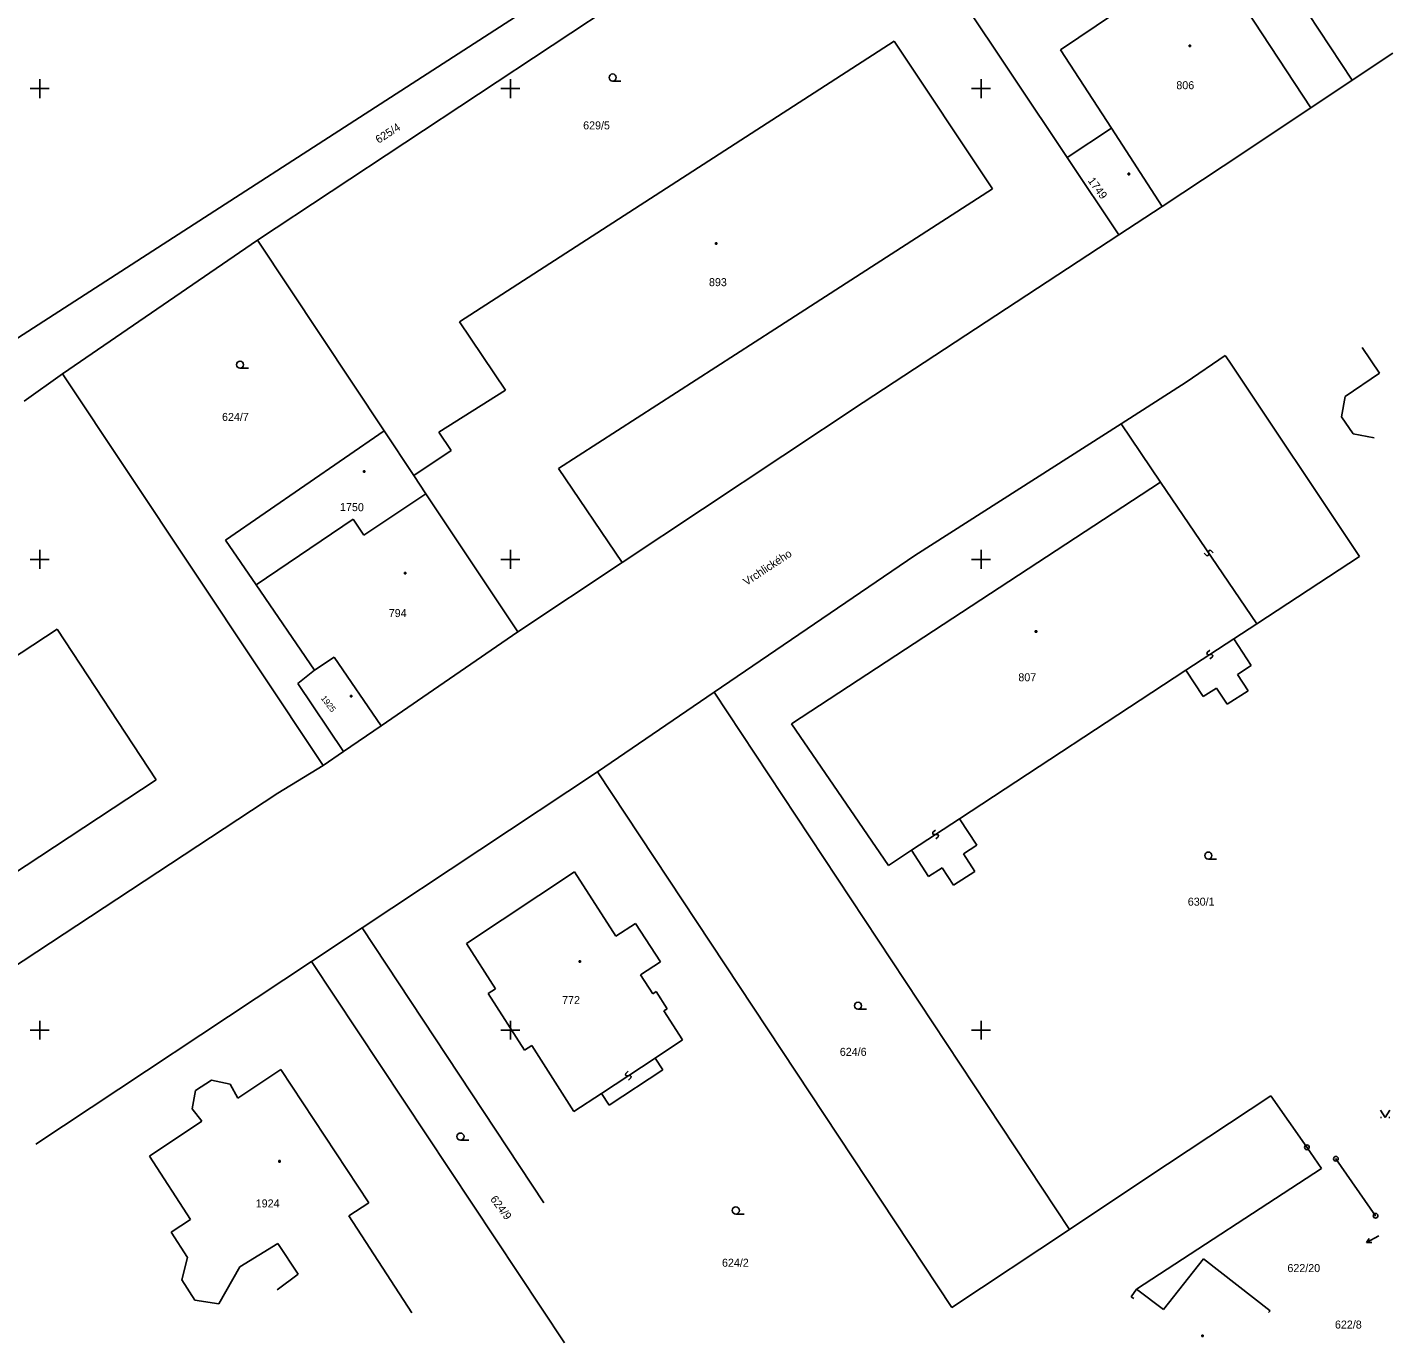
# Model space of a CAD drawing. Extents: x -493352 to -492964, y -1127001 to -1126712.
# Drawn here: x -493050.8 to -492963.8, y -1126999.9 to -1126916.1 of the extents above; entities that cross this region are included whole.
import ezdxf

# ---------------------------------------------------------------- set-up
doc = ezdxf.new("R2010")
doc.units = 0
doc.layers.add('katastrální mapa', color=7, linetype='Continuous')
doc.layers.add('síť', color=7, linetype='Continuous')

msp = doc.modelspace()

# ---------------------------------------------------------------- linework, layer by layer
at = {"layer": 'katastrální mapa'}
for p, q in [((-492982.85, -1126894.43), (-492966.34, -1126919.47)), ((-493036.12, -1126929.67), (-492997.86, -1126904.36)), ((-492997.86, -1126904.36), (-492984.51, -1126924.39)), ((-493063.66, -1126943.8), (-493007.98, -1126907.88)), ((-492974.44, -1126912.93), (-492968.97, -1126921.22)), ((-492984.93, -1126917.52), (-492981.49, -1126915.21)), ((-493009.39, -1126925.92), (-492995.53, -1126916.98)), ((-492995.53, -1126916.98), (-492989.27, -1126926.39)), ((-492984.93, -1126917.52), (-492981.68, -1126922.53)), ((-492976.74, -1126917.23), (-492976.65, -1126917.23)), ((-492976.74, -1126917.32), (-492976.74, -1126917.23)), ((-492976.65, -1126917.32), (-492976.74, -1126917.32)), ((-492976.65, -1126917.23), (-492976.65, -1126917.32)), ((-492966.34, -1126919.47), (-492963.76, -1126917.75)), ((-493013.48, -1126919.52), (-493012.95, -1126919.52)), ((-492968.97, -1126921.22), (-492966.34, -1126919.47)), ((-492974.56, -1126924.95), (-492968.97, -1126921.22)), ((-492984.51, -1126924.39), (-492981.68, -1126922.53)), ((-492981.68, -1126922.53), (-492978.46, -1126927.51)), ((-492984.51, -1126924.39), (-492981.22, -1126929.32)), ((-492978.46, -1126927.51), (-492974.56, -1126924.95)), ((-493023.25, -1126934.87), (-493009.39, -1126925.92)), ((-492980.62, -1126925.4), (-492980.53, -1126925.4)), ((-492980.62, -1126925.49), (-492980.62, -1126925.4)), ((-492980.53, -1126925.49), (-492980.62, -1126925.49)), ((-492980.53, -1126925.4), (-492980.53, -1126925.49)), ((-493003.14, -1126935.33), (-492989.27, -1126926.39)), ((-492981.22, -1126929.32), (-492978.46, -1126927.51)), ((-493048.54, -1126938.17), (-493036.12, -1126929.67)), ((-493036.12, -1126929.67), (-493028.04, -1126941.82)), ((-492997.52, -1126940.01), (-492981.22, -1126929.32)), ((-493006.92, -1126929.82), (-493006.83, -1126929.82)), ((-493006.92, -1126929.91), (-493006.92, -1126929.82)), ((-493006.83, -1126929.91), (-493006.92, -1126929.91)), ((-493006.83, -1126929.82), (-493006.83, -1126929.91)), ((-493023.25, -1126934.87), (-493020.31, -1126939.22)), ((-493016.93, -1126944.22), (-493003.14, -1126935.33)), ((-492965.71, -1126936.49), (-492964.6, -1126938.13)), ((-492976.92, -1126938.7), (-492974.44, -1126937.01)), ((-492974.44, -1126937.01), (-492974.18, -1126937.38)), ((-492974.18, -1126937.38), (-492965.88, -1126949.81)), ((-493050.98, -1126939.91), (-493048.54, -1126938.17)), ((-493048.54, -1126938.17), (-493031.94, -1126963.13)), ((-493037.23, -1126937.82), (-493036.7, -1126937.82)), ((-492966.79, -1126939.62), (-492964.6, -1126938.13)), ((-493024.56, -1126941.9), (-493020.31, -1126939.22)), ((-492981.07, -1126941.36), (-492976.92, -1126938.7)), ((-493012.88, -1126950.21), (-492997.52, -1126940.01)), ((-492967.03, -1126940.91), (-492966.79, -1126939.62)), ((-492967.03, -1126940.91), (-492966.27, -1126942.01)), ((-493038.16, -1126948.78), (-493028.04, -1126941.82)), ((-493028.04, -1126941.82), (-493026.16, -1126944.65)), ((-492994.21, -1126949.76), (-492981.07, -1126941.36)), ((-492981.07, -1126941.36), (-492978.55, -1126945.08)), ((-493024.56, -1126941.9), (-493023.78, -1126943.07)), ((-492966.27, -1126942.01), (-492964.94, -1126942.25)), ((-493026.16, -1126944.65), (-493023.78, -1126943.07)), ((-493029.37, -1126944.36), (-493029.28, -1126944.36)), ((-493029.37, -1126944.45), (-493029.37, -1126944.36)), ((-493029.28, -1126944.45), (-493029.37, -1126944.45)), ((-493029.28, -1126944.36), (-493029.28, -1126944.45)), ((-493016.93, -1126944.22), (-493012.88, -1126950.21)), ((-493026.16, -1126944.65), (-493025.38, -1126945.82)), ((-493002.07, -1126960.49), (-492978.55, -1126945.08)), ((-492978.55, -1126945.08), (-492972.43, -1126954.11)), ((-493029.33, -1126948.45), (-493025.38, -1126945.82)), ((-493025.38, -1126945.82), (-493019.52, -1126954.62)), ((-493036.21, -1126951.63), (-493030.01, -1126947.43)), ((-493030.01, -1126947.43), (-493029.33, -1126948.45)), ((-493038.16, -1126948.78), (-493036.21, -1126951.63)), ((-492975.63, -1126949.76), (-492975.77, -1126949.61)), ((-492975.48, -1126949.45), (-492975.5, -1126949.53)), ((-492975.5, -1126949.53), (-492975.48, -1126949.66)), ((-492975.48, -1126949.66), (-492975.5, -1126949.74)), ((-492975.43, -1126949.41), (-492975.48, -1126949.45)), ((-492975.35, -1126949.43), (-492975.43, -1126949.41)), ((-492975.21, -1126949.58), (-492975.35, -1126949.43)), ((-493019.52, -1126954.62), (-493012.88, -1126950.21)), ((-493007, -1126958.47), (-492994.21, -1126949.76)), ((-492975.55, -1126949.78), (-492975.63, -1126949.76)), ((-492975.5, -1126949.74), (-492975.55, -1126949.78)), ((-492972.43, -1126954.11), (-492965.88, -1126949.81)), ((-493026.75, -1126950.84), (-493026.66, -1126950.84)), ((-493026.75, -1126950.93), (-493026.75, -1126950.84)), ((-493026.66, -1126950.93), (-493026.75, -1126950.93)), ((-493026.66, -1126950.84), (-493026.66, -1126950.93)), ((-493036.21, -1126951.63), (-493032.48, -1126957.07)), ((-493063.3, -1126963.95), (-493048.88, -1126954.44)), ((-493048.88, -1126954.44), (-493042.57, -1126964.05)), ((-493028.24, -1126960.6), (-493019.52, -1126954.62)), ((-492986.54, -1126954.55), (-492986.45, -1126954.55)), ((-492986.54, -1126954.64), (-492986.54, -1126954.55)), ((-492986.45, -1126954.64), (-492986.54, -1126954.64)), ((-492986.45, -1126954.55), (-492986.45, -1126954.64)), ((-492973.89, -1126955.07), (-492972.43, -1126954.11)), ((-492976.94, -1126957.07), (-492973.89, -1126955.07)), ((-492975.42, -1126955.79), (-492975.58, -1126955.93)), ((-492973.89, -1126955.07), (-492972.79, -1126956.77)), ((-493032.48, -1126957.07), (-493031.24, -1126956.23)), ((-493031.24, -1126956.23), (-493028.24, -1126960.6)), ((-492975.58, -1126955.93), (-492975.6, -1126956.01)), ((-492975.6, -1126956.01), (-492975.56, -1126956.06)), ((-492975.56, -1126956.06), (-492975.48, -1126956.08)), ((-492975.48, -1126956.08), (-492975.35, -1126956.06)), ((-492975.25, -1126956.21), (-492975.41, -1126956.35)), ((-492975.35, -1126956.06), (-492975.27, -1126956.08)), ((-492975.27, -1126956.08), (-492975.23, -1126956.13)), ((-492975.23, -1126956.13), (-492975.25, -1126956.21)), ((-493033.54, -1126957.91), (-493032.48, -1126957.07)), ((-492991.37, -1126966.53), (-492976.94, -1126957.07)), ((-492976.94, -1126957.07), (-492975.84, -1126958.75)), ((-492973.65, -1126957.33), (-492972.79, -1126956.77)), ((-492973.65, -1126957.33), (-492972.97, -1126958.37)), ((-493033.54, -1126957.91), (-493030.63, -1126962.24)), ((-492975.84, -1126958.75), (-492974.98, -1126958.2)), ((-492974.98, -1126958.2), (-492974.31, -1126959.22)), ((-492974.31, -1126959.22), (-492972.97, -1126958.37)), ((-493030.19, -1126958.67), (-493030.1, -1126958.67)), ((-493030.19, -1126958.76), (-493030.19, -1126958.67)), ((-493030.1, -1126958.76), (-493030.19, -1126958.76)), ((-493030.1, -1126958.67), (-493030.1, -1126958.76)), ((-493014.44, -1126963.54), (-493007, -1126958.47)), ((-493007, -1126958.47), (-492984.37, -1126992.7)), ((-493030.63, -1126962.24), (-493028.24, -1126960.6)), ((-493002.07, -1126960.49), (-492995.9, -1126969.5)), ((-493031.94, -1126963.13), (-493030.63, -1126962.24)), ((-493034.83, -1126964.91), (-493031.94, -1126963.13)), ((-493029.45, -1126973.48), (-493014.44, -1126963.54)), ((-493014.44, -1126963.54), (-492991.86, -1126997.68)), ((-493057.08, -1126973.59), (-493042.57, -1126964.05)), ((-493055.85, -1126978.73), (-493034.83, -1126964.91)), ((-492994.43, -1126968.54), (-492991.37, -1126966.53)), ((-492991.37, -1126966.53), (-492990.27, -1126968.22)), ((-492993.07, -1126967.39), (-492993.08, -1126967.48)), ((-492993.08, -1126967.48), (-492993.05, -1126967.53)), ((-492992.91, -1126967.25), (-492993.07, -1126967.39)), ((-492993.05, -1126967.53), (-492992.97, -1126967.54)), ((-492992.97, -1126967.54), (-492992.83, -1126967.53)), ((-492992.73, -1126967.68), (-492992.89, -1126967.82)), ((-492992.83, -1126967.53), (-492992.75, -1126967.54)), ((-492992.75, -1126967.54), (-492992.72, -1126967.59)), ((-492992.72, -1126967.59), (-492992.73, -1126967.68)), ((-492995.9, -1126969.5), (-492994.43, -1126968.54)), ((-492994.43, -1126968.54), (-492993.34, -1126970.22)), ((-492991.12, -1126968.77), (-492990.27, -1126968.22)), ((-492991.12, -1126968.77), (-492990.39, -1126969.9)), ((-492993.34, -1126970.22), (-492992.48, -1126969.66)), ((-492992.48, -1126969.66), (-492991.75, -1126970.77)), ((-492975.51, -1126969.1), (-492974.98, -1126969.1)), ((-493022.8, -1126974.48), (-493015.92, -1126969.91)), ((-493015.92, -1126969.91), (-493013.28, -1126974.01)), ((-492991.75, -1126970.77), (-492990.39, -1126969.9)), ((-493013.28, -1126974.01), (-493012.02, -1126973.2)), ((-493012.02, -1126973.2), (-493010.44, -1126975.65)), ((-493032.67, -1126975.62), (-493029.45, -1126973.48)), ((-493029.45, -1126973.48), (-493017.86, -1126991)), ((-493022.8, -1126974.48), (-493020.95, -1126977.36)), ((-493050.24, -1126987.27), (-493032.67, -1126975.62)), ((-493032.67, -1126975.62), (-493016.55, -1126999.92)), ((-493015.61, -1126975.58), (-493015.52, -1126975.58)), ((-493015.61, -1126975.67), (-493015.61, -1126975.58)), ((-493015.52, -1126975.67), (-493015.61, -1126975.67)), ((-493015.52, -1126975.58), (-493015.52, -1126975.67)), ((-493011.7, -1126976.47), (-493010.44, -1126975.65)), ((-493011.7, -1126976.47), (-493010.91, -1126977.69)), ((-493021.42, -1126977.66), (-493020.95, -1126977.36)), ((-493010.91, -1126977.69), (-493010.7, -1126977.55)), ((-493010.7, -1126977.55), (-493010, -1126978.64)), ((-493021.42, -1126977.66), (-493019.1, -1126981.28)), ((-493010.21, -1126978.78), (-493010, -1126978.64)), ((-493010.21, -1126978.78), (-493009.02, -1126980.63)), ((-492997.84, -1126978.67), (-492997.31, -1126978.67)), ((-493019.1, -1126981.28), (-493018.64, -1126980.99)), ((-493018.64, -1126980.99), (-493015.96, -1126985.18)), ((-493010.77, -1126981.78), (-493009.02, -1126980.63)), ((-493014.2, -1126984.03), (-493010.77, -1126981.78)), ((-493010.77, -1126981.78), (-493010.28, -1126982.53)), ((-493037.37, -1126984.33), (-493034.64, -1126982.51)), ((-493034.64, -1126982.51), (-493029.03, -1126991.01)), ((-493013.71, -1126984.78), (-493010.28, -1126982.53)), ((-493012.65, -1126982.76), (-493012.67, -1126982.85)), ((-493012.49, -1126982.62), (-493012.65, -1126982.76)), ((-493040.06, -1126983.84), (-493039.04, -1126983.2)), ((-493039.04, -1126983.2), (-493037.87, -1126983.45)), ((-493037.87, -1126983.45), (-493037.37, -1126984.33)), ((-493012.67, -1126982.85), (-493012.63, -1126982.9)), ((-493012.63, -1126982.9), (-493012.55, -1126982.91)), ((-493012.55, -1126982.91), (-493012.42, -1126982.9)), ((-493012.32, -1126983.05), (-493012.48, -1126983.19)), ((-493012.42, -1126982.9), (-493012.34, -1126982.91)), ((-493012.34, -1126982.91), (-493012.3, -1126982.96)), ((-493012.3, -1126982.96), (-493012.32, -1126983.05)), ((-493040.28, -1126985.01), (-493040.06, -1126983.84)), ((-493015.96, -1126985.18), (-493014.2, -1126984.03)), ((-493014.2, -1126984.03), (-493013.71, -1126984.78)), ((-492979.44, -1126989.42), (-492971.52, -1126984.19)), ((-492971.52, -1126984.19), (-492969.23, -1126987.47)), ((-493040.28, -1126985.01), (-493039.67, -1126985.8)), ((-492964.54, -1126985.11), (-492964.24, -1126985.56)), ((-492964.24, -1126985.56), (-492963.94, -1126985.11)), ((-493043, -1126988.04), (-493039.67, -1126985.8)), ((-492964.54, -1126985.56), (-492964.48, -1126985.56)), ((-492964, -1126985.56), (-492963.94, -1126985.56)), ((-493023.18, -1126987.01), (-493022.65, -1126987.01)), ((-492969.23, -1126987.47), (-492968.29, -1126988.83)), ((-493043, -1126988.04), (-493040.39, -1126992.07)), ((-493034.76, -1126988.32), (-493034.67, -1126988.32)), ((-493034.76, -1126988.41), (-493034.76, -1126988.32)), ((-493034.67, -1126988.41), (-493034.76, -1126988.41)), ((-493034.67, -1126988.32), (-493034.67, -1126988.41)), ((-492980.09, -1126996.51), (-492968.29, -1126988.83)), ((-492964.85, -1126991.83), (-492967.38, -1126988.2)), ((-492984.37, -1126992.7), (-492979.44, -1126989.42)), ((-493030.29, -1126991.84), (-493029.03, -1126991.01)), ((-493041.62, -1126992.88), (-493040.39, -1126992.07)), ((-493030.29, -1126991.84), (-493026.28, -1126998.01)), ((-493005.63, -1126991.72), (-493005.1, -1126991.72)), ((-493041.62, -1126992.88), (-493040.57, -1126994.5)), ((-492991.86, -1126997.68), (-492984.37, -1126992.7)), ((-492964.65, -1126993.11), (-492965.44, -1126993.54)), ((-493037.24, -1126995.08), (-493034.82, -1126993.6)), ((-493034.82, -1126993.6), (-493033.52, -1126995.56)), ((-492965.44, -1126993.54), (-492965.25, -1126993.27)), ((-492965.44, -1126993.54), (-492965.1, -1126993.53)), ((-493040.93, -1126995.91), (-493040.57, -1126994.5)), ((-492978.36, -1126997.81), (-492975.82, -1126994.57)), ((-492975.82, -1126994.57), (-492971.58, -1126997.89)), ((-493038.58, -1126997.45), (-493037.24, -1126995.08)), ((-493034.87, -1126996.56), (-493033.52, -1126995.56)), ((-493040.93, -1126995.91), (-493040.11, -1126997.22)), ((-492980.44, -1126996.99), (-492980.09, -1126996.51)), ((-492980.09, -1126996.51), (-492978.36, -1126997.81)), ((-493040.11, -1126997.22), (-493038.58, -1126997.45)), ((-492980.44, -1126996.99), (-492980.27, -1126997.11)), ((-492971.58, -1126997.89), (-492971.67, -1126997.99)), ((-492975.93, -1126999.44), (-492975.84, -1126999.44)), ((-492975.93, -1126999.53), (-492975.93, -1126999.44)), ((-492975.84, -1126999.53), (-492975.93, -1126999.53)), ((-492975.84, -1126999.44), (-492975.84, -1126999.53))]:
    msp.add_line(p, q, dxfattribs=at)
for centre, radius in [((-493013.48, -1126919.295), 0.225), ((-493037.23, -1126937.595), 0.225), ((-492975.51, -1126968.875), 0.225), ((-492997.84, -1126978.445), 0.225), ((-493023.18, -1126986.785), 0.225), ((-492969.23, -1126987.47), 0.15), ((-492969.23, -1126987.47), 0.003), ((-492967.38, -1126988.2), 0.15), ((-492967.38, -1126988.2), 0.003), ((-493005.63, -1126991.495), 0.225), ((-492964.85, -1126991.83), 0.15), ((-492964.85, -1126991.83), 0.003)]:
    msp.add_circle(centre, radius, dxfattribs=at)
at = {"layer": 'síť'}
for p, q in [((-493050.6, -1126920), (-493049.4, -1126920)), ((-493050, -1126919.4), (-493050, -1126920.6)), ((-493020.6, -1126920), (-493019.4, -1126920)), ((-493020, -1126919.4), (-493020, -1126920.6)), ((-492990.6, -1126920), (-492989.4, -1126920)), ((-492990, -1126919.4), (-492990, -1126920.6)), ((-493050, -1126949.4), (-493050, -1126950.6)), ((-493020, -1126949.4), (-493020, -1126950.6)), ((-492990, -1126949.4), (-492990, -1126950.6)), ((-493050.6, -1126950), (-493049.4, -1126950)), ((-493020.6, -1126950), (-493019.4, -1126950)), ((-492990.6, -1126950), (-492989.4, -1126950)), ((-493050.6, -1126980), (-493049.4, -1126980)), ((-493050, -1126979.4), (-493050, -1126980.6)), ((-493020.6, -1126980), (-493019.4, -1126980)), ((-493020, -1126979.4), (-493020, -1126980.6)), ((-492990.6, -1126980), (-492989.4, -1126980)), ((-492990, -1126979.4), (-492990, -1126980.6))]:
    msp.add_line(p, q, dxfattribs=at)

# ---------------------------------------------------------------- texts
at = {"layer": 'katastrální mapa'}
for s, height, p in [('806', 0.51, (-492977.55, -1126920.04)), ('629/5', 0.51, (-493015.36, -1126922.6)), ('893', 0.51, (-493007.34, -1126932.59)), ('624/7', 0.51, (-493038.38, -1126941.18)), ('794', 0.51, (-493027.75, -1126953.68)), ('807', 0.51, (-492987.62, -1126957.77)), ('630/1', 0.51, (-492976.82, -1126972.07)), ('772', 0.51, (-493016.7, -1126978.34)), ('624/6', 0.51, (-492999, -1126981.64)), ('1924', 0.51, (-493036.23, -1126991.3)), ('622/20', 0.03, (-492964.65, -1126993.11)), ('624/2', 0.51, (-493006.51, -1126995.08)), ('622/20', 0.51, (-492970.47, -1126995.42)), ('622/8', 0.51, (-492967.44, -1126999.02))]:
    msp.add_text(s, height=height, dxfattribs=at).set_placement(p)
for s, height, rotation, p in [('625/4', 0.51, 32.886, (-493028.39, -1126923.52)), ('1749', 0.51, 306.36, (-492983.22, -1126925.88)), ('1750', 0.51, 358.956, (-493030.86, -1126946.91)), ('Vrchlického', 0.50999, 33.399, (-493004.95, -1126951.7)), ('1925', 0.39, 307.449, (-493032.1, -1126958.86)), ('624/9', 0.51, 306.765, (-493021.31, -1126990.78))]:
    msp.add_text(s, height=height, rotation=rotation, dxfattribs=at).set_placement(p)

doc.saveas('drawing.dxf')
